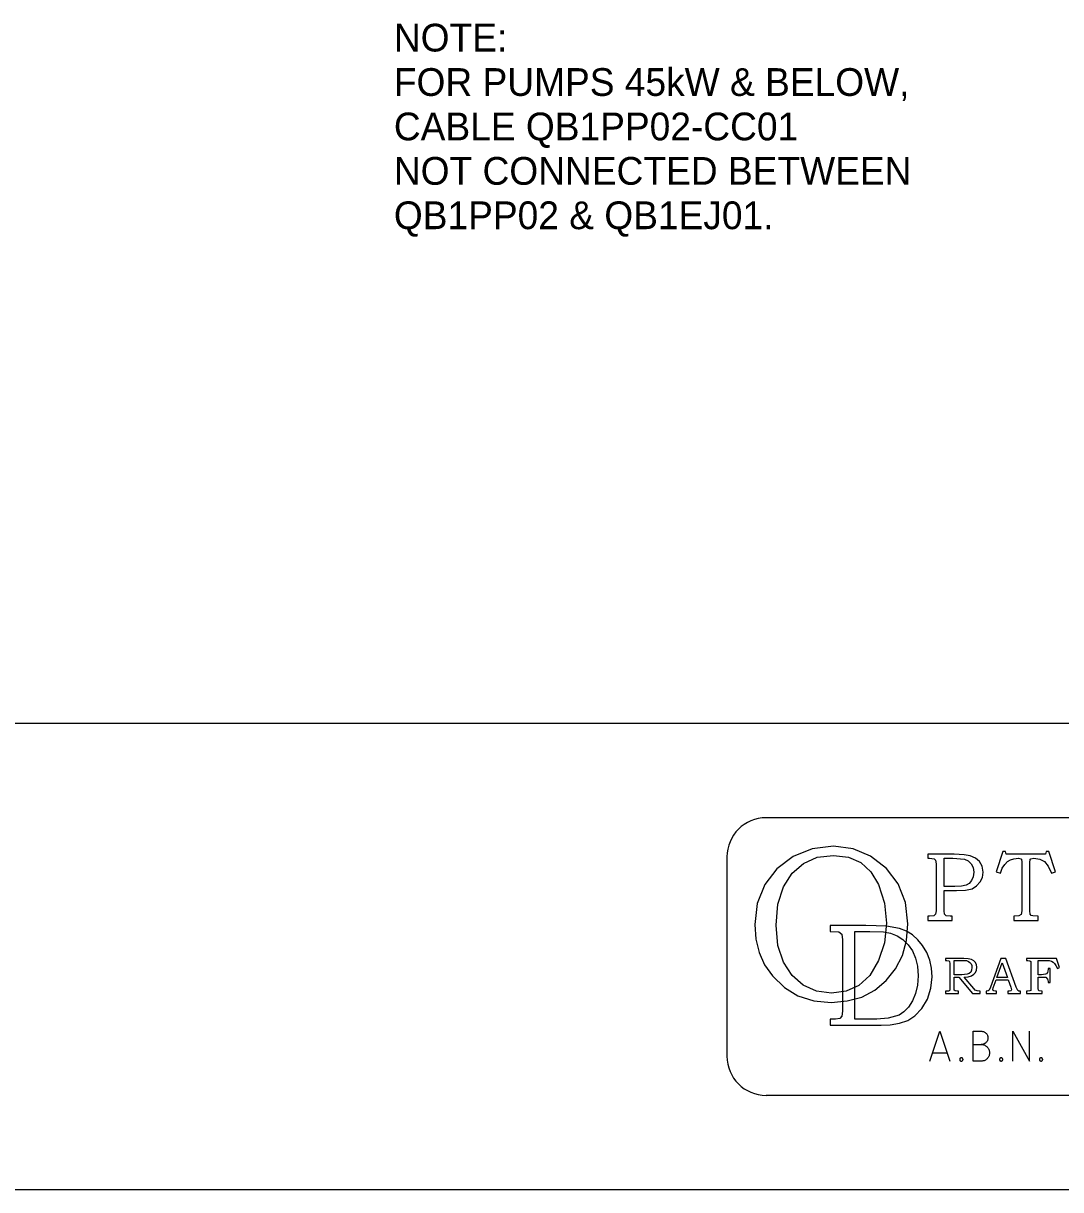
# Model space of a CAD drawing. Extents: x 0 to 841, y 0 to 594.
# Drawn here: x 446.6 to 540.1, y 15 to 120 of the extents above; entities that cross this region are included whole.
import ezdxf

# ---------------------------------------------------------------- set-up
doc = ezdxf.new("R2010")
doc.units = 0
for name, color, linetype in [('A1BORDER', 7, 'Continuous'), ('INSTALLED', 7, 'Continuous'), ('Level 1', 7, 'Continuous'), ('Level 10', 7, 'Continuous')]:
    doc.layers.add(name, color=color, linetype=linetype)

msp = doc.modelspace()

# ---------------------------------------------------------------- linework, layer by layer
at = {"layer": 'A1BORDER'}
for p, q in [((28, 57), (829, 57)), ((829, 15), (28, 15))]:
    msp.add_line(p, q, dxfattribs=at)
at = {"layer": 'Level 1'}
for points in [[(519.59, 45.93), (517.69, 45.7), (515.96, 45), (514.48, 43.9), (513.4, 42.47), (512.73, 40.77), (512.5, 38.87), (512.6, 37.57), (512.9, 36.37), (513.39, 35.25), (514.1, 34.25), (515.17, 33.2), (516.4, 32.45), (517.82, 32), (519.4, 31.87), (520.84, 32), (522.14, 32.35), (523.32, 32.97), (524.34, 33.83), (525.19, 34.9), (525.8, 36.1), (526.17, 37.45), (526.28, 38.95), (526.07, 40.85), (525.42, 42.53), (524.37, 43.93), (522.94, 45.03), (521.36, 45.7)], [(519.6, 45.1), (520.96, 44.93), (522.06, 44.45), (522.96, 43.63), (523.66, 42.47), (524.18, 40.8), (524.36, 39), (524.18, 37.23), (523.66, 35.63), (522.86, 34.3), (521.88, 33.4), (520.73, 32.87), (519.42, 32.7), (518.08, 32.87), (516.88, 33.43), (515.88, 34.3), (515.1, 35.5), (514.59, 37), (514.43, 38.83), (514.59, 40.7), (515.1, 42.27), (515.89, 43.5), (516.9, 44.37), (518.14, 44.93)], [(519.3, 38.25), (520.07, 38.23), (520.34, 38), (520.4, 37.5), (520.4, 31.07), (520.36, 30.63), (520.16, 30.43), (519.78, 30.35), (519.67, 30.35), (519.3, 30.35), (519.3, 29.8), (523.88, 29.8), (524.7, 29.85), (525.53, 30), (526.28, 30.25), (526.93, 30.67), (527.56, 31.33), (528.06, 32.17), (528.38, 33.15), (528.5, 34.17), (528.44, 34.95), (528.28, 35.67), (528, 36.37), (527.62, 37), (527.18, 37.5), (526.7, 37.95), (526.16, 38.27), (525.54, 38.53), (524.36, 38.73), (522.5, 38.8), (519.3, 38.8)], [(521.52, 30.35), (521.52, 38.25), (522.88, 38.25), (524.09, 38.23), (524.74, 38.1), (525.32, 37.87), (525.84, 37.53), (526.32, 37.05), (526.7, 36.5), (526.99, 35.85), (527.16, 35.13), (527.22, 34.27), (527.16, 33.43), (526.99, 32.67), (526.72, 32), (526.36, 31.45), (525.93, 31.03), (525.5, 30.73), (524.52, 30.45), (523.5, 30.35)], [(529.69, 35.83), (529.69, 35.63), (529.82, 35.63), (529.98, 35.6), (530.06, 35.55), (530.09, 35.37), (530.09, 33.13), (530.08, 32.97), (530.03, 32.9), (529.96, 32.87), (529.8, 32.87), (529.69, 32.87), (529.69, 32.67), (530.86, 32.67), (530.86, 32.87), (530.77, 32.87), (530.56, 32.9), (530.48, 32.97), (530.47, 33.13), (530.47, 34.15), (530.89, 34.15), (532.13, 32.67), (532.8, 32.67), (532.8, 32.87), (532.74, 32.87), (532.54, 32.9), (532.37, 32.97), (532.23, 33.13), (531.38, 34.15), (531.74, 34.17), (532.03, 34.27), (532.24, 34.4), (532.4, 34.57), (532.49, 34.77), (532.52, 35.03), (532.49, 35.25), (532.4, 35.45), (532.24, 35.6), (532.04, 35.73), (531.74, 35.8), (531.33, 35.83)], [(534.66, 35.83), (533.74, 33.23), (533.63, 32.97), (533.53, 32.9), (533.34, 32.87), (533.34, 32.67), (534.27, 32.67), (534.27, 32.87), (534.18, 32.87), (534.03, 32.9), (533.98, 32.93), (533.96, 33.03), (533.98, 33.17), (534.24, 33.9), (535.33, 33.9), (535.56, 33.25), (535.63, 33), (535.6, 32.95), (535.56, 32.9), (535.42, 32.87), (535.3, 32.87), (535.3, 32.67), (536.44, 32.67), (536.44, 32.87), (536.39, 32.87), (536.28, 32.87), (536.2, 32.93), (536.13, 33.05), (536.06, 33.23), (535.12, 35.83)], [(536.99, 35.83), (536.99, 35.63), (537.1, 35.63), (537.28, 35.6), (537.36, 35.55), (537.38, 35.37), (537.38, 33.13), (537.36, 32.95), (537.28, 32.9), (537.08, 32.87), (536.99, 32.87), (536.99, 32.67), (538.4, 32.67), (538.4, 32.87), (538.32, 32.87), (538.13, 32.9), (538.06, 32.97), (538.02, 33.13), (538.02, 34.15), (538.37, 34.15), (538.72, 34.13), (538.87, 33.97), (538.9, 33.87), (538.92, 33.75), (538.92, 33.65), (539.1, 33.65), (539.1, 34.93), (538.92, 34.93), (538.92, 34.85), (538.9, 34.67), (538.87, 34.55), (538.79, 34.45), (538.69, 34.4), (538.34, 34.35), (538.02, 34.35), (538.02, 35.63), (538.72, 35.63), (539.02, 35.63), (539.22, 35.57), (539.37, 35.5), (539.5, 35.37), (539.63, 35.2), (539.76, 34.93), (539.96, 35), (539.69, 35.83)], [(530.47, 35.63), (531.33, 35.63), (531.59, 35.63), (531.77, 35.55), (531.89, 35.47), (531.99, 35.35), (532.06, 35.2), (532.07, 35), (532.04, 34.77), (531.97, 34.6), (531.82, 34.47), (531.64, 34.4), (531.16, 34.35), (530.47, 34.35)], [(534.32, 34.1), (534.78, 35.43), (535.26, 34.1)]]:
    msp.add_lwpolyline(points, close=True, dxfattribs=at)
for points in [[(528.28, 26.57), (529.18, 29.26), (530.07, 26.57)], [(532.17, 28.06), (532.9, 28.06), (532.98, 28.06), (533.04, 28.06), (533.1, 28.04), (533.17, 28.03), (533.23, 28), (533.28, 27.96), (533.34, 27.93), (533.39, 27.89), (533.44, 27.85), (533.48, 27.8), (533.52, 27.75), (533.56, 27.69), (533.59, 27.64), (533.62, 27.57), (533.63, 27.51), (533.64, 27.45), (533.66, 27.39), (533.66, 27.33), (533.66, 27.25), (533.64, 27.19), (533.63, 27.13), (533.62, 27.06), (533.59, 27), (533.56, 26.95), (533.52, 26.89), (533.48, 26.84), (533.44, 26.79), (533.39, 26.75), (533.34, 26.71), (533.28, 26.67), (533.23, 26.64), (533.17, 26.61), (533.1, 26.6), (533.04, 26.59), (532.98, 26.57), (532.9, 26.57), (532.17, 26.57), (532.17, 29.26), (532.9, 29.26), (532.96, 29.26), (533.02, 29.25), (533.07, 29.24), (533.12, 29.23), (533.17, 29.2), (533.2, 29.19), (533.26, 29.15), (533.29, 29.13), (533.33, 29.09), (533.37, 29.05), (533.4, 29.01), (533.43, 28.96), (533.46, 28.91), (533.47, 28.86), (533.49, 28.81), (533.49, 28.77), (533.5, 28.71), (533.5, 28.66), (533.5, 28.61), (533.49, 28.56), (533.49, 28.51), (533.47, 28.46), (533.46, 28.41), (533.43, 28.36), (533.4, 28.33), (533.37, 28.27), (533.33, 28.24), (533.29, 28.2), (533.26, 28.17), (533.2, 28.15), (533.17, 28.13), (533.12, 28.1), (533.07, 28.09), (533.02, 28.07), (532.96, 28.06), (532.9, 28.06)], [(535.76, 26.57), (535.76, 29.26), (537.24, 26.57), (537.24, 29.26)], [(528.58, 27.33), (529.77, 27.33)], [(530.97, 26.73), (530.97, 26.71), (530.97, 26.7), (530.97, 26.69), (530.98, 26.67), (530.98, 26.66), (530.98, 26.65), (530.99, 26.64), (530.99, 26.63), (531, 26.61), (531.02, 26.61), (531.03, 26.6), (531.04, 26.59), (531.06, 26.59), (531.07, 26.59), (531.08, 26.57), (531.09, 26.57), (531.1, 26.57), (531.12, 26.57), (531.13, 26.57), (531.14, 26.57), (531.16, 26.57), (531.17, 26.59), (531.18, 26.59), (531.19, 26.59), (531.2, 26.6), (531.2, 26.61), (531.22, 26.61), (531.23, 26.63), (531.23, 26.64), (531.24, 26.65), (531.26, 26.66), (531.26, 26.67), (531.26, 26.69), (531.27, 26.7), (531.27, 26.71), (531.27, 26.73), (531.27, 26.74), (531.27, 26.75), (531.26, 26.76), (531.26, 26.77), (531.26, 26.79), (531.24, 26.8), (531.23, 26.81), (531.23, 26.81), (531.22, 26.83), (531.2, 26.84), (531.2, 26.85), (531.19, 26.85), (531.18, 26.86), (531.17, 26.86), (531.16, 26.86), (531.14, 26.87), (531.13, 26.87), (531.12, 26.87), (531.1, 26.87), (531.09, 26.87), (531.08, 26.86), (531.07, 26.86), (531.06, 26.86), (531.04, 26.85), (531.03, 26.85), (531.02, 26.84), (531, 26.83), (530.99, 26.81), (530.99, 26.81), (530.98, 26.8), (530.98, 26.79), (530.98, 26.77), (530.97, 26.76), (530.97, 26.75), (530.97, 26.74), (530.97, 26.73)], [(534.56, 26.73), (534.56, 26.71), (534.56, 26.7), (534.56, 26.69), (534.56, 26.67), (534.57, 26.66), (534.57, 26.65), (534.58, 26.64), (534.58, 26.63), (534.59, 26.61), (534.6, 26.61), (534.62, 26.6), (534.63, 26.59), (534.64, 26.59), (534.64, 26.59), (534.66, 26.57), (534.68, 26.57), (534.69, 26.57), (534.7, 26.57), (534.72, 26.57), (534.73, 26.57), (534.74, 26.57), (534.76, 26.59), (534.77, 26.59), (534.78, 26.59), (534.78, 26.6), (534.79, 26.61), (534.8, 26.61), (534.82, 26.63), (534.82, 26.64), (534.83, 26.65), (534.83, 26.66), (534.84, 26.67), (534.84, 26.69), (534.84, 26.7), (534.84, 26.71), (534.86, 26.73), (534.84, 26.74), (534.84, 26.75), (534.84, 26.76), (534.84, 26.77), (534.83, 26.79), (534.83, 26.8), (534.82, 26.81), (534.82, 26.81), (534.8, 26.83), (534.79, 26.84), (534.78, 26.85), (534.78, 26.85), (534.77, 26.86), (534.76, 26.86), (534.74, 26.86), (534.73, 26.87), (534.72, 26.87), (534.7, 26.87), (534.69, 26.87), (534.68, 26.87), (534.66, 26.86), (534.64, 26.86), (534.64, 26.86), (534.63, 26.85), (534.62, 26.85), (534.6, 26.84), (534.59, 26.83), (534.58, 26.81), (534.58, 26.81), (534.57, 26.8), (534.57, 26.79), (534.56, 26.77), (534.56, 26.76), (534.56, 26.75), (534.56, 26.74), (534.56, 26.73)], [(538.14, 26.73), (538.14, 26.71), (538.14, 26.7), (538.14, 26.69), (538.16, 26.67), (538.16, 26.66), (538.16, 26.65), (538.17, 26.64), (538.17, 26.63), (538.18, 26.61), (538.19, 26.61), (538.2, 26.6), (538.22, 26.59), (538.23, 26.59), (538.24, 26.59), (538.26, 26.57), (538.27, 26.57), (538.28, 26.57), (538.29, 26.57), (538.3, 26.57), (538.32, 26.57), (538.33, 26.57), (538.34, 26.59), (538.36, 26.59), (538.37, 26.59), (538.38, 26.6), (538.38, 26.61), (538.39, 26.61), (538.4, 26.63), (538.4, 26.64), (538.42, 26.65), (538.43, 26.66), (538.43, 26.67), (538.43, 26.69), (538.44, 26.7), (538.44, 26.71), (538.44, 26.73), (538.44, 26.74), (538.44, 26.75), (538.43, 26.76), (538.43, 26.77), (538.43, 26.79), (538.42, 26.8), (538.4, 26.81), (538.4, 26.81), (538.39, 26.83), (538.38, 26.84), (538.38, 26.85), (538.37, 26.85), (538.36, 26.86), (538.34, 26.86), (538.33, 26.86), (538.32, 26.87), (538.3, 26.87), (538.29, 26.87), (538.28, 26.87), (538.27, 26.87), (538.26, 26.86), (538.24, 26.86), (538.23, 26.86), (538.22, 26.85), (538.2, 26.85), (538.19, 26.84), (538.18, 26.83), (538.17, 26.81), (538.17, 26.81), (538.16, 26.8), (538.16, 26.79), (538.16, 26.77), (538.14, 26.76), (538.14, 26.75), (538.14, 26.74), (538.14, 26.73)]]:
    msp.add_lwpolyline(points, dxfattribs=at)
at = {"layer": 'Level 10'}
for p, q in [((571.47, 48.5), (513.54, 48.5)), ((510, 44.97), (510, 27.03)), ((513.54, 23.5), (571.47, 23.5)), ((513.54, 23.5), (513.54, 23.5))]:
    msp.add_line(p, q, dxfattribs=at)
for points in [[(528.1, 45.2), (528.1, 44.85), (528.24, 44.85), (528.66, 44.8), (528.79, 44.67), (528.84, 44.35), (528.84, 40.1), (528.79, 39.8), (528.63, 39.67), (528.24, 39.63), (528.1, 39.63), (528.1, 39.25), (530.29, 39.25), (530.29, 39.63), (530.1, 39.63), (529.74, 39.67), (529.6, 39.8), (529.57, 40.1), (529.57, 41.93), (530.68, 41.93), (531.49, 41.97), (532.08, 42.1), (532.49, 42.35), (532.82, 42.73), (533.02, 43.1), (533.09, 43.6), (533, 44.13), (532.76, 44.55), (532.38, 44.85), (531.92, 45.07), (531.36, 45.15), (530.46, 45.2)], [(534.86, 45.45), (534.26, 43.63), (534.63, 43.5), (534.8, 43.95), (535.03, 44.27), (535.28, 44.55), (535.54, 44.7), (535.84, 44.8), (536.26, 44.85), (536.47, 44.8), (536.53, 44.75), (536.56, 44.5), (536.56, 40.1), (536.5, 39.77), (536.29, 39.65), (535.83, 39.63), (535.83, 39.25), (538.02, 39.25), (538.02, 39.63), (537.56, 39.65), (537.4, 39.7), (537.32, 39.8), (537.29, 40.1), (537.29, 44.43), (537.32, 44.75), (537.37, 44.8), (537.64, 44.85), (538.18, 44.75), (538.6, 44.55), (538.94, 44.13), (539.22, 43.5), (539.59, 43.63), (538.99, 45.45), (538.74, 45.45), (538.7, 45.2), (535.14, 45.2), (535.1, 45.45)], [(529.57, 44.85), (530.34, 44.85), (531.4, 44.75), (531.74, 44.6), (532, 44.35), (532.19, 44), (532.24, 43.6), (532.19, 43.17), (532.04, 42.85), (531.82, 42.57), (531.56, 42.43), (531.14, 42.33), (530.53, 42.3), (529.57, 42.3)]]:
    msp.add_lwpolyline(points, close=True, dxfattribs=at)
for centre, start, end in [((513.54, 44.96), 90, 180), ((513.54, 27.03), 180, 270)]:
    msp.add_arc(centre, 3.54, start, end, dxfattribs=at)

# ---------------------------------------------------------------- texts
at = {"layer": 'INSTALLED'}
for s, p in [('NOTE:', (480, 117.5)), ('FOR PUMPS 45kW & BELOW,', (480, 113.5)), ('CABLE QB1PP02-CC01', (480, 109.5)), ('NOT CONNECTED BETWEEN', (480, 105.5)), ('QB1PP02 & QB1EJ01.', (480, 101.5))]:
    msp.add_text(s, height=2.5, dxfattribs=at).set_placement(p)

doc.saveas('drawing.dxf')
